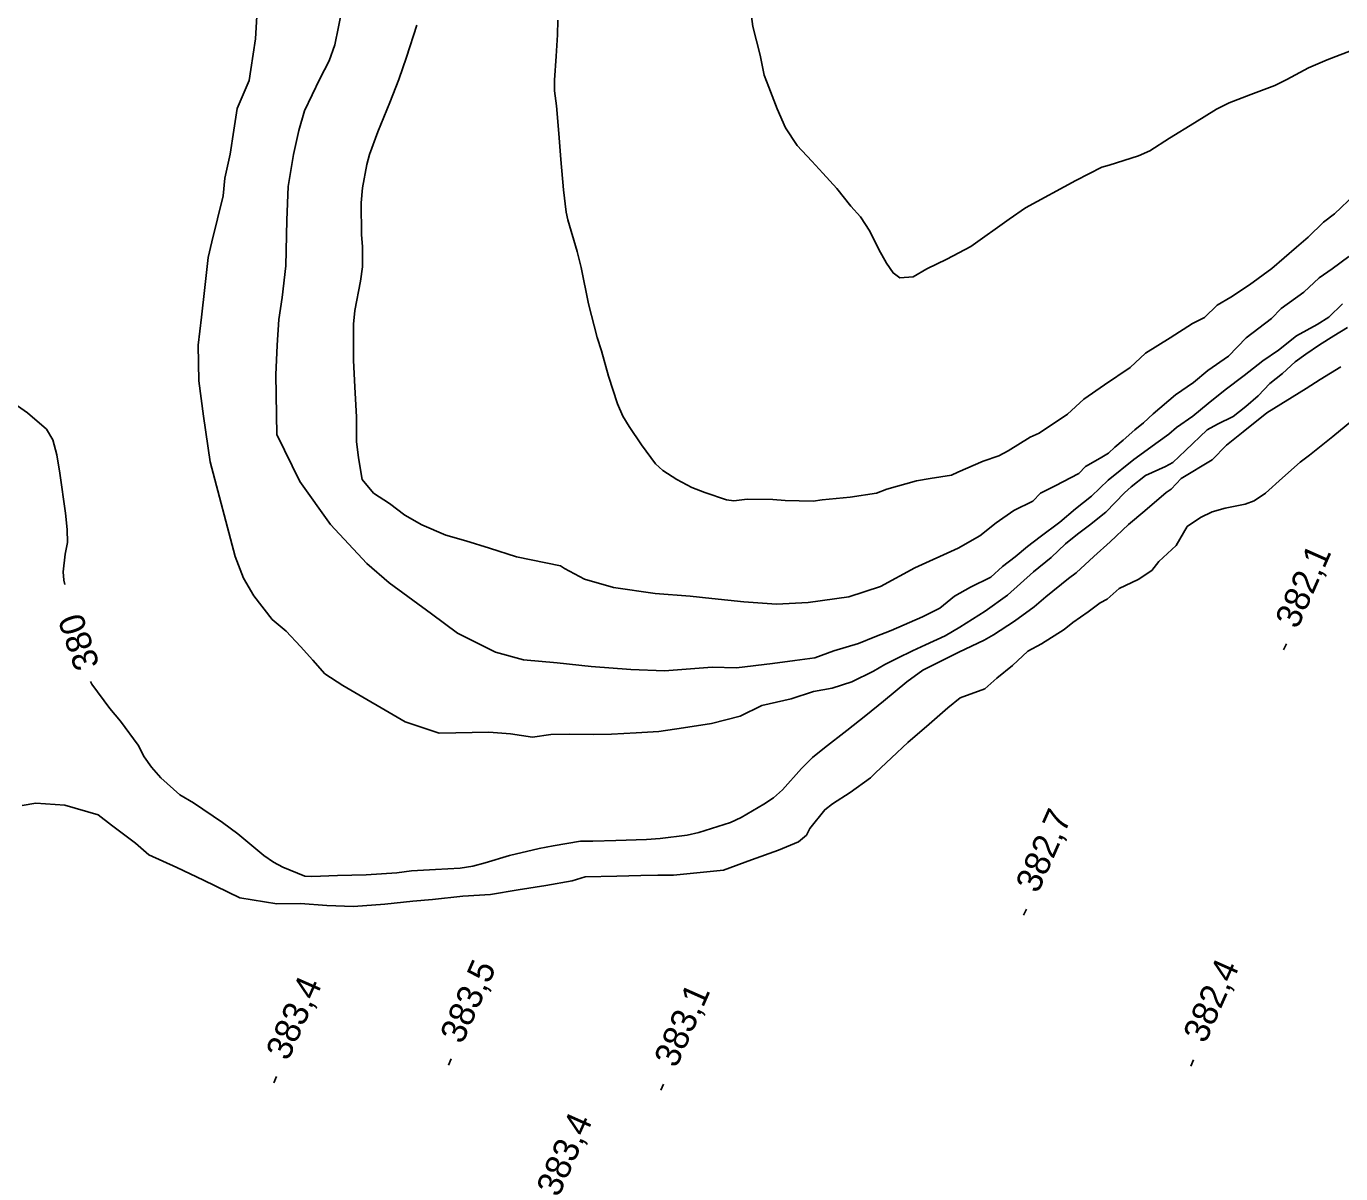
# Model space of a CAD drawing. Extents: x 287698 to 290158, y 5234163 to 5237182.
# Drawn here: x 288115.1 to 288270.6, y 5235215.8 to 5235351.5 of the extents above; entities that cross this region are included whole.
import ezdxf

# ---------------------------------------------------------------- set-up
doc = ezdxf.new("R2010")
doc.units = 0
for name, color, linetype in [('Niveau 1', 7, 'Continuous'), ('Niveau 2', 7, 'Continuous'), ('Niveau 3', 7, 'Continuous')]:
    doc.layers.add(name, color=color, linetype=linetype)

msp = doc.modelspace()

# ---------------------------------------------------------------- linework, layer by layer
at = {"layer": 'Niveau 1'}
for points in [[(288200.43, 5235356.3), (288201.03, 5235351.48), (288201.93, 5235348.09), (288202.4, 5235345.72), (288202.94, 5235344.29), (288203.92, 5235341.75), (288204.89, 5235339.48), (288206.29, 5235337.39), (288208.03, 5235335.56), (288209.33, 5235334.14), (288210.98, 5235332.31), (288212.63, 5235330.22), (288213.77, 5235328.97), (288214.9, 5235327.29), (288215.96, 5235325.1), (288216.84, 5235323.51), (288217.63, 5235322.33), (288218.41, 5235321.76), (288220.02, 5235321.88), (288221.61, 5235322.84), (288223.97, 5235323.98), (288226.83, 5235325.48), (288231.35, 5235328.71), (288233.28, 5235330.02), (288239.25, 5235333.27), (288242.31, 5235334.84), (288243.18, 5235335.07), (288246.64, 5235336.19), (288248.01, 5235336.78)], [(288248.01, 5235336.78), (288250.33, 5235338.27), (288253.26, 5235340.08), (288255.87, 5235341.69), (288257.37, 5235342.46), (288259.93, 5235343.45), (288262.76, 5235344.51), (288264.18, 5235345.21), (288266.75, 5235346.59), (288268.98, 5235347.53), (288272.34, 5235348.82)], [(288148.91, 5235250.95), (288151.94, 5235251.06), (288155.31, 5235251.17), (288158.94, 5235251.39), (288160.67, 5235251.64), (288163.5, 5235251.78), (288166.42, 5235251.94), (288167.92, 5235252.18), (288169.37, 5235252.59), (288172.28, 5235253.46), (288175.79, 5235254.29), (288177.45, 5235254.59), (288180.65, 5235255.12), (288182.13, 5235255.15), (288184.86, 5235255.22), (288188.48, 5235255.32), (288190.09, 5235255.46), (288193.27, 5235255.85), (288194.64, 5235256.17), (288198.39, 5235257.33), (288199.67, 5235257.92), (288202.35, 5235259.5), (288203.49, 5235260.27), (288204.56, 5235261.22), (288206.79, 5235263.74), (288208.11, 5235265.02), (288209.52, 5235266.17), (288212.15, 5235268.21), (288214.4, 5235269.98), (288216.5, 5235271.71), (288219.25, 5235273.98), (288221.16, 5235275.36), (288222.81, 5235276.19), (288225.42, 5235277.49), (288228.39, 5235278.9), (288229.5, 5235279.55), (288231.98, 5235281.16), (288234.31, 5235282.85), (288235.71, 5235284.04), (288238.36, 5235286.22), (288239.29, 5235286.89), (288241.37, 5235288.79), (288243.3, 5235290.53), (288245.49, 5235292.57), (288247.42, 5235294.19), (288249.91, 5235296.38), (288250.51, 5235296.75), (288251.71, 5235298.02), (288255.36, 5235300.22), (288257.05, 5235301.96), (288259.05, 5235303.56), (288261.82, 5235305.81), (288266.47, 5235308.69), (288268.15, 5235309.72), (288270.59, 5235311.23)], [(288114.09, 5235306.61), (288115.27, 5235305.78), (288117.5, 5235303.85), (288118.28, 5235302.59), (288118.73, 5235300.84), (288119.08, 5235298.64), (288119.75, 5235293.92), (288119.97, 5235292), (288119.99, 5235290.47), (288119.71, 5235289.06), (288119.49, 5235286.98), (288119.56, 5235286.02), (288119.69, 5235285.49)], [(288122.7, 5235274.01), (288122.86, 5235273.7), (288125.02, 5235270.83), (288126.25, 5235269.32), (288128.36, 5235266.48), (288129.07, 5235265.12), (288129.92, 5235263.87), (288131.04, 5235262.63), (288133.28, 5235260.63), (288134.91, 5235259.67), (288138.31, 5235257.35), (288140.12, 5235256.02), (288143.21, 5235253.46), (288144.34, 5235252.65), (288145.47, 5235252.08), (288148.06, 5235251), (288148.91, 5235250.95)]]:
    msp.add_lwpolyline(points, dxfattribs=at)
at = {"layer": 'Niveau 2'}
for points in [[(288152.49, 5235353.56), (288151.63, 5235349.32), (288150.96, 5235347.44), (288149.84, 5235345.31), (288148.03, 5235341.52), (288147.37, 5235339.17), (288146.72, 5235336.33), (288146.09, 5235332.57), (288145.93, 5235328.59), (288145.8, 5235323.19), (288145.4, 5235319.43), (288144.98, 5235316.84), (288144.8, 5235313.79), (288144.64, 5235310.27), (288144.77, 5235303.24), (288147.46, 5235297.67), (288151.08, 5235292.57), (288155.4, 5235287.97), (288158.02, 5235285.68), (288163.03, 5235282.02), (288166.12, 5235279.73), (288170.63, 5235277.48), (288173.92, 5235276.6), (288177.92, 5235276.21), (288181.92, 5235275.81), (288186.62, 5235275.43), (288190.61, 5235275.28), (288196.23, 5235275.72), (288199.11, 5235275.65), (288203.38, 5235276.15), (288206.01, 5235276.49), (288208.36, 5235276.83), (288210.63, 5235277.63)], [(288142.39, 5235352.7), (288142.23, 5235350.02), (288141.67, 5235346.4), (288141.47, 5235345.08), (288140.07, 5235341.8), (288139.65, 5235339.21), (288139.23, 5235336.39), (288138.59, 5235333.56), (288138.39, 5235331.44), (288137.08, 5235326.02), (288136.65, 5235324.15), (288136.25, 5235320.62), (288135.85, 5235317.1), (288135.45, 5235313.8), (288135.53, 5235309.59), (288136.08, 5235305.38), (288136.88, 5235300), (288139.83, 5235288.79), (288140.82, 5235286.23), (288142.03, 5235284.14), (288144.19, 5235281.36), (288145.87, 5235279.99), (288147.55, 5235278.14), (288148.99, 5235276.53), (288150.43, 5235274.92), (288152.57, 5235273.55), (288159.92, 5235269.24), (288163.94, 5235267.9), (288169.81, 5235268.02), (288172.39, 5235267.84), (288174.98, 5235267.42), (288177.15, 5235267.76), (288179.38, 5235267.8), (288182.2, 5235267.74), (288184.32, 5235267.78), (288187.24, 5235267.95), (288189.94, 5235268.11), (288192.86, 5235268.53), (288196.14, 5235269.05), (288199.53, 5235269.94), (288202.09, 5235271.17), (288205.58, 5235271.97), (288208.21, 5235272.84), (288210.43, 5235273.23), (288212.75, 5235273.98), (288215.32, 5235275.26), (288216.66, 5235276.05), (288218.16, 5235276.78), (288219.91, 5235277.63), (288221.48, 5235278.37), (288223.8, 5235279.41), (288225.54, 5235280.44), (288228.51, 5235282.32), (288231.17, 5235284.24), (288234.23, 5235287), (288236.31, 5235288.68), (288238.04, 5235290.3), (288239.43, 5235291.44), (288240.87, 5235292.52), (288242.8, 5235294.06), (288244.98, 5235296.33), (288245.79, 5235297.05), (288247.5, 5235298.38)], [(288161.3, 5235351.62), (288160.1, 5235347.86), (288159.17, 5235345.2), (288158.1, 5235342.51), (288156.68, 5235339.03), (288155.72, 5235336.36), (288155.41, 5235335.18), (288154.9, 5235332.41), (288154.72, 5235330.62), (288154.75, 5235326.84), (288154.9, 5235325.48), (288154.88, 5235323.06), (288154.65, 5235321.38), (288153.98, 5235317.88), (288153.81, 5235316.26), (288153.81, 5235314.71), (288153.82, 5235311.97), (288153.98, 5235308.85), (288154.19, 5235305.27), (288154.16, 5235302.39), (288154.39, 5235300.48), (288154.84, 5235297.91), (288156.18, 5235296.31), (288158.08, 5235295.06), (288159.87, 5235293.68), (288161.88, 5235292.55), (288164.73, 5235291.32), (288167.09, 5235290.66), (288169.92, 5235289.78), (288173.11, 5235288.78), (288178.29, 5235287.71), (288178.77, 5235287.37), (288181.14, 5235286.12), (288184.56, 5235285.14), (288189.51, 5235284.41), (288193.62, 5235284.13), (288196.21, 5235283.83), (288199.97, 5235283.43), (288203.86, 5235283.16), (288207.6, 5235283.35), (288212.4, 5235284.02), (288216.14, 5235285.27), (288220.21, 5235287.46), (288225.32, 5235289.78), (288227.88, 5235291.24), (288229.84, 5235292.8), (288231.93, 5235294.25), (288234.14, 5235295.35), (288235.06, 5235296.3), (288236.81, 5235297.15), (288239.59, 5235298.62), (288240.39, 5235299.45), (288242.13, 5235300.43)], [(288177.99, 5235352.23), (288177.95, 5235350.5), (288177.77, 5235347.99), (288177.59, 5235345.15), (288177.6, 5235343.87), (288177.83, 5235342.09), (288178.1, 5235338.81), (288178.32, 5235335.77), (288178.64, 5235332.16), (288178.95, 5235329.54), (288179.17, 5235328.6), (288180.27, 5235324.88), (288180.74, 5235322.97), (288181.6, 5235318.7), (288182.63, 5235314.72), (288183.15, 5235313.14), (288183.98, 5235310.14), (288185.04, 5235306.87), (288185.69, 5235305.38), (288186.4, 5235304.17), (288187.88, 5235301.99), (288189.53, 5235299.78), (288190.41, 5235298.97), (288192.06, 5235297.91), (288193.84, 5235296.98), (288195.36, 5235296.38), (288197.92, 5235295.52), (288198.8, 5235295.4), (288200.38, 5235295.58), (288203.41, 5235295.56), (288204.87, 5235295.41), (288208.19, 5235295.33), (288209.26, 5235295.5), (288212.56, 5235295.83), (288215.68, 5235296.28), (288216.88, 5235296.76), (288220.4, 5235297.75), (288222.03, 5235298.03), (288224.54, 5235298.44), (288225.3, 5235298.77), (288228.3, 5235300.07), (288230.15, 5235300.7), (288231.23, 5235301.3), (288233.86, 5235302.9), (288234.9, 5235303.4), (288238.24, 5235305.62), (288240.2, 5235307.42), (288242.64, 5235309.11), (288245.65, 5235311.16), (288247.49, 5235312.83), (288250.39, 5235314.65), (288253.06, 5235316.34), (288254.46, 5235317.07), (288255.95, 5235318.51), (288257.57, 5235319.48), (288259.77, 5235320.93), (288262.44, 5235322.85), (288265.33, 5235325.37), (288266.72, 5235326.57), (288268.55, 5235328.36), (288269.83, 5235329.33), (288272.25, 5235331.6)], [(288242.13, 5235300.43), (288243.1, 5235301.01), (288243.85, 5235301.72), (288244.83, 5235302.56), (288246.21, 5235303.77), (288247.26, 5235304.61), (288248.4, 5235305.68), (288251.05, 5235307.93), (288253.14, 5235309.37), (288254.87, 5235310.81), (288257.3, 5235312.5), (288259.38, 5235314.65), (288262.38, 5235316.94), (288263.53, 5235318.13), (288266.19, 5235320.06), (288268.04, 5235321.74), (288269.54, 5235322.82), (288271.51, 5235324.27)], [(288210.63, 5235277.63), (288213.55, 5235278.51), (288215.47, 5235279.31), (288217.4, 5235280.06), (288221.12, 5235281.65), (288223.16, 5235282.69), (288224.89, 5235284.12), (288226.8, 5235285.16), (288229.19, 5235286.37), (288230.58, 5235287.63), (288232.08, 5235288.78), (288233.52, 5235289.98), (288235.03, 5235291.12), (288237.34, 5235292.86), (288239.19, 5235294.42), (288241.1, 5235295.93), (288243.05, 5235297.84), (288246.09, 5235300.26), (288248.98, 5235302.37), (288250.26, 5235303.27), (288251.13, 5235304.06), (288253.09, 5235305.39), (288254.88, 5235306.88), (288256.9, 5235308.5), (288259.16, 5235310.19), (288261.36, 5235311.93), (288263.21, 5235313.2), (288265.35, 5235314.89), (288267.8, 5235316.22), (288269.18, 5235317.12), (288270.8, 5235318.68)], [(288247.5, 5235298.38), (288249.85, 5235299.43), (288250.72, 5235299.93), (288252.2, 5235301.33), (288254.76, 5235303.77), (288255.99, 5235304.44), (288257.84, 5235305.36), (288259.35, 5235306.56), (288260.8, 5235307.82), (288262.18, 5235309.25), (288263.68, 5235310.45), (288265.18, 5235311.83), (288266.45, 5235312.74), (288268.07, 5235313.82), (288269.75, 5235314.91), (288271.39, 5235315.87)], [(288246.62, 5235286.1), (288248.25, 5235287.16), (288249.05, 5235288.21), (288251.09, 5235290.11), (288252.42, 5235292.34), (288253.99, 5235293.42), (288255.35, 5235294.07), (288256.9, 5235294.51), (288259.27, 5235294.98), (288260.35, 5235295.38), (288261.69, 5235296.3), (288263.69, 5235298.11), (288265.76, 5235299.94), (288266.86, 5235300.79), (288269.65, 5235303.01), (288271.89, 5235304.85)], [(288114.63, 5235259.35), (288116.26, 5235259.64), (288119.68, 5235259.41), (288123.61, 5235258.25), (288125.2, 5235257.03), (288128.05, 5235254.9), (288129.63, 5235253.52), (288132.94, 5235252.02), (288136.09, 5235250.52), (288140.36, 5235248.43), (288144.74, 5235247.73), (288147.55, 5235247.78), (288150.68, 5235247.53), (288153.8, 5235247.43), (288157.54, 5235247.67), (288160.82, 5235248.04), (288163.16, 5235248.24), (288166.74, 5235248.62), (288170.02, 5235248.84), (288173.29, 5235249.37), (288176.56, 5235249.9), (288179.67, 5235250.43), (288181.22, 5235250.93), (288184.97, 5235251), (288187.78, 5235251.06), (288189.81, 5235251.1), (288191.68, 5235251.13), (288197.57, 5235251.72), (288200.88, 5235252.94), (288204.09, 5235254.08), (288206.46, 5235255.06), (288207.38, 5235255.85), (288207.78, 5235256.64), (288209.54, 5235258.86), (288210.46, 5235259.57), (288212.57, 5235260.89), (288214.96, 5235262.62), (288215.56, 5235263.22), (288217.43, 5235265.01), (288219.36, 5235266.81), (288221.88, 5235268.96), (288224.09, 5235270.9), (288225.58, 5235272.1), (288228.48, 5235273.17), (288229.91, 5235274.43), (288231.74, 5235275.91), (288233.57, 5235277.6), (288235.2, 5235278.46), (288237.85, 5235280.16), (288238.87, 5235281), (288240.7, 5235282.27), (288242.13, 5235283.33), (288242.94, 5235283.76), (288244.37, 5235285.03), (288246.62, 5235286.1)]]:
    msp.add_lwpolyline(points, dxfattribs=at)
at = {"layer": 'Niveau 3'}
for p, q in [((288263.82, 5235277.75), (288264.14, 5235278.48)), ((288233.07, 5235246.38), (288233.39, 5235247.11)), ((288165.05, 5235228.66), (288165.37, 5235229.39)), ((288252.84, 5235228.54), (288253.16, 5235229.27)), ((288144.4, 5235226.57), (288144.72, 5235227.3)), ((288190.16, 5235225.68), (288190.48, 5235226.41))]:
    msp.add_line(p, q, dxfattribs=at)

# ---------------------------------------------------------------- texts
at = {"layer": 'Niveau 1'}
msp.add_text('380', height=3, rotation=109.0144, dxfattribs=at).set_placement((288123.83, 5235275.99))
at = {"layer": 'Niveau 3'}
for s, p in [('382,1', (288265.45, 5235280.12)), ('382,7', (288234.75, 5235248.86)), ('383,5', (288166.68, 5235231.03)), ('382,4', (288254.56, 5235231.11)), ('383,4', (288146.08, 5235229.05)), ('383,1', (288191.99, 5235228.21)), ('383,4', (288178.07, 5235212.93))]:
    msp.add_text(s, height=3, rotation=66.1217, dxfattribs=at).set_placement(p)

doc.saveas('drawing.dxf')
